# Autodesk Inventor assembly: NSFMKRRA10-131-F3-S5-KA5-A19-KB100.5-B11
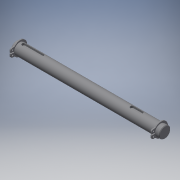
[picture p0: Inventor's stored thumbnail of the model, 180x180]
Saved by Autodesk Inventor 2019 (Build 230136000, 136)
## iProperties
Category: PARTsolutions
Company: MISUMI
Created: 2022-11
Part Number: NSFMKRRA10-131-F3-S5-KA5-A19-KB100.5-B11
Catalog Web Link: www.cadenas.de
Description: NSFMKRR, SFMKRR, PSFMKRR, SSFMKRR, NSFHKRR, SFHKRR, PSFHKRR, SSFHKRR, NSFGKRR, SFGKRR, PSFGKRR, SSFGKRR, NSFMKRRA, SFMKRRA, PSFMKRRA, SSFMKRRA, NSFHKRRA, SFHKRR
Vendor: MISUMI
Document SubType Name: Assembly
Designer: psAdmin
Manufacturer: MISUMI
Mass: 10.2368 g
Surface Area: 47.8895 cm^2
Volume: 10.2368 cm^3
Density: 1 g/cm^3
Title: NSFMKRRA10-131-F3-S5-KA5-A19-KB100.5-B11
Author: Cadenas PARTsolutions
Comments: Rotary Shafts - Retaining Ring Grooves on Both Ends with Keyway -
PSOL_IDENT_0: {$CADENAS_DATA/23d-libs/misumi/metric/11_rotary_shafts/psfgkrr_asmtab.prj},644 {VTYP=3D},{STYP=ASSTA
PSOL_IDENT_1: B},{NB=NSFMKRRA10-131-F3-S5-KA5-A19-KB100.5-B11},{LINA=NSFMKRRA10-131-F3-S5-KA5-A19-KB100.5-B11},{NN=
PSOL_IDENT_2: NSFMKRR, SFMKRR, PSFMKRR, SSFMKRR, NSFHKRR, SFHKRR, PSFHKRR, SSFHKRR, NSFGKRR, SFGKRR, PSFGKRR, SSFG
PSOL_IDENT_3: KRR, NSFMKRRA, SFMKRRA, PSFMKRRA, SSFMKRRA, NSFHKRRA, SFHKRRA, PSFHKRRA, SSFHKRRA, NSFGKRRA, SFGKRRA
PSOL_IDENT_4: , PSFGKRRA, SSFGKRRA},{DATE=25.01.2022 23:09:58},{GEOMDATE=05.02.2021 08:16:43},{VERSION=},{LINEID=3
PSOL_IDENT_5: 0},{WBVAR=TS,TYS,MAT,ST,ALT1,L,F,S,NOK,KA,A,KB,B,KC,C,ALT3,FC,GALT3,WFC,J,WALT3,V,ALT4,SFC,SG,AG,ALT
PSOL_IDENT_6: 10,KWC,ALT11,WC,ALT5,UC,ALT7,SC,ALT32,CD},{WBNUMERIC=L,F,S,KA,A,KB,B,KC,C,FC,GALT3,WFC,J,WALT3,V,SFC
PSOL_IDENT_7: ,SG,AG,KWC,WC,UC,SC}  {NB=NSFMKRRA10-131-F3-S5-KA5-A19-KB100.5-B11},{LINA=NSFMKRRA10-131-F3-S5-KA5-A
PSOL_IDENT_8: 19-KB100.5-B11},{KT=DUMMY},{PN=NSFMKRRA10-131-F3-S5-KA5-A19-KB100.5-B11},{TS=A},{TSALG='','Standard'
PSOL_IDENT_9: ,'A','Retaining Ring'},{TYS=M},{TYSALG= 'M','h9 (Cold-drawn)','H','h7 (Ground)','G','g6 (Ground)' },
PSOL_IDENT_10: {MAT=S45C},{MATALG= 'S45C','S45C Equivalent', 'SUS304','304 Stainless Steel' },{ST=},{STALG= '','-','
PSOL_IDENT_11: BO','Black Oxide', 'ENP','Electroless Nickel Plating' },{TYPE=NSFMKRR},{D=10},{ALT1=},{LKCMAX=799.9}
PSOL_IDENT_12: ,{L=131.0},{LALG=[15:800/0.1]},{LMIN=15},{LMAX=800},{F=3.0},{FALG=[3:126/0.1]},{FMIN=3},{FMAX1=122.8
PSOL_IDENT_13: },{FMIN2=6.2},{FMAX2=126},{S=5.0},{SALG=[3:126/0.1]},{SMIN1=3},{SMAX1=121},{SMIN2=6.2},{SMAX2=126},{
PSOL_IDENT_14: DD=9.6},{MM=1.15},{MMALG=1.2},{MMJ=2},{NOK=2},{NOKALG= '1', 'with 1 Key Groove', '2'  , 'with 2 Key
PSOL_IDENT_15: Grooves', '3'  , 'with 3 Key Grooves'},{CIFNOK1=0},{CIFNOK2=3},{CIFNOK3=0},{TOL1=0},{TOL2=3},{TOL3=0
PSOL_IDENT_16: },{BB=3},{TT=1.8},{KA=5.0},{KAALG=[5:116/0.1]},{KAMIN1=0},{KAMIN2=5},{KAMIN3=129.2},{KAMAX1=-1000},{
PSOL_IDENT_17: KAMAX2=116},{KAMAX3=-1000},{A=19.0},{AALG=[3:100/0.1]},{AMIN=3},{AMAX=100},{AMAX1=-1000},{AMAX2=100}
PSOL_IDENT_18: ,{AMAX3=-1000},{KAPN=-KA5-A19},{KB=100.5},{KBALG=[26:121/0.1]},{KBMIN1=26},{KBMIN2=26},{KBMIN3=129.2
PSOL_IDENT_19: },{KBMAX1=-1000},{KBMAX2=121},{KBMAX3=-1000},{B=11.0},{BALG=[3:23.5/0.1]},{BMIN=3},{BMAX=23.5},{BMAX
PSOL_IDENT_20: 1=-1000},{BMAX2=23.5},{BMAX3=-1000},{KBPN=-KB100.5-B11},{KC=0.0},{KCALG=[0]},{KCMIN1=113.5},{KCMIN2=
PSOL_IDENT_21: 113.5},{KCMIN3=129.2},{KCMAX1=-1000},{KCMAX2=-1000},{KCMAX3=-1000},{C=0.0},{CALG=0},{CMIN=3},{CMAX=-
PSOL_IDENT_22: 1000},{CMAX1=-1000},{CMAX2=-1000},{CMAX3=-1000},{CIFKA=5},{CIFKB=3},{CIFKC=3},{KCPN=},{ALT3=},{ALT3A
PSOL_IDENT_23: LG= '', 'w/o Set Screw Flat','FC','with FC (Adds a Set Screw Flat)','WFC','with WFC (Adds Two Set Sc
PSOL_IDENT_24: rew Flats)','FCWFC','with FC + WFC (Adds Three Set Screw Flats)' },{ALT3PN=},{FC=0},{FCALG=[0]},{FCM
PSOL_IDENT_25: IN=0},{FCMAX=130},{GALT3=0},{GALT3ALG=[0]},{GALT3MIN=1},{GALT3MAX=70},{GALT3MAX2=70},{GALT3MAX3=70},
PSOL_IDENT_26: {WFC=0},{WFCALG=[0]},{WFCMIN=0},{WFCMIN2=2},{WFCMAX=127},{WFCMAX2=-3},{WFCMAX3=-4},{J=0},{JALG=[0]},
PSOL_IDENT_27: {JMIN=1},{JMAX=70},{JMAX2=-2},{JMAX3=-5},{WALT3=0},{WALT3ALG=[0]},{WALT3MIN=0},{WALT3MIN2=133},{WALT
PSOL_IDENT_28: 3MAX=128},{WALT3MAX2=128},{V=0},{VALG=[0]},{VMIN=1},{VMAX=70},{VMAX2=70},{CIFFC=0},{ALT4=},{ALT4ALG=
PSOL_IDENT_29: '', 'w/o SFC (2 Set Screw Flats (Angle Specified))', 'SFC'  , 'with SFC (2 Set Screw Flats (Angle S
PSOL_IDENT_30: pecified))'},{ALT4PN=},{SFC=0},{SFCALG=[0]},{SFCMIN=0},{SFCMAX=130},{SG=0},{SGALG=[0]},{SGMIN=1},{SG
PSOL_IDENT_31: MAX=70},{AG=0},{AGALG=[0]},{H=0},{CIFSFC=0},{ALT10=},{ALT10ALG= '','Not applicable' },{KWC=0},{KWCAL
PSOL_IDENT_32: G=[0]},{KWCMIN=1},{KWCMAX=0},{WALT10=8},{ALT10PN=},{ALT11=},{ALT11ALG= '','Not applicable' },{WC=0.0
PSOL_IDENT_33: },{WCALG=[0]},{ALT11PN=},{ALT5=},{ALT5ALG= '', 'w/o UC (Slit Cam Groove)', 'UC', 'with UC (Slit Cam
PSOL_IDENT_34: Groove)'},{ALT5PN=},{UC=0},{UCALG=[0]},{UCMIN=1},{UCMAX=125},{DDALT5=0},{LL1=0},{ALT7=},{ALT7ALG= ''
PSOL_IDENT_35: , 'w/o SC (Wrench Flats)', 'SC', 'with SC (Wrench Flats)'},{ALT7PN=},{SC=0},{SCALG=[0]},{SCMIN=0},{S
PSOL_IDENT_36: CMAX=123},{LL2=0},{LL2ALG=8},{WALT7=0},{CIFSC=0},{ALT32=},{ALT32ALG= '','w/o CD (Changes Part D Cham
PSOL_IDENT_37: fering)','CD','with CD (Changes Part D Chamfering)' },{CD=},{CDALG= '','N/A' },{CD3D=0.5},{ALT32PN=}
PSOL_IDENT_38: ,{CIF323R=0},{CIF323L=0},{CIF324R=0},{CIF324L=0},{CIF3210=0},{CIF32F=0},{CIF32S=0},{ERRORPN=},{ERROR
PSOL_IDENT_39: KGALT3=OK},{ERRORKGALT4=OK},{ERRORKGALT5=OK},{ERRORKGALT7=OK},{ERRORKGALT10=OK},{ERRORRALT3=OK},{ERR
PSOL_IDENT_40: ORRALT4=NG},{ERRORRALT5=NG},{ERRORRALT7=NG},{ERRORRALT10=OK},{ERRORALT34=OK},{ERRORALT35=OK},{ERRORA
PSOL_IDENT_41: LT37=OK},{ERRORALT310=OK},{ERRORALT45=OK},{ERRORALT47=OK},{ERRORALT410=OK},{ERRORALT57=OK},{ERRORALT
PSOL_IDENT_42: 510=OK},{ERRORALT710=OK},{PCUT3D=0},{QCUT3D=0},{TTALT2=1.8},{BBALT2=3},{PPATH=11_components/psfgkrr/
PSOL_IDENT_43: psfgkrr_asmtpl.prj}
NB: NSFMKRRA10-131-F3-S5-KA5-A19-KB100.5-B11
NN: NSFMKRR, SFMKRR, PSFMKRR, SSFMKRR, NSFHKRR, SFHKRR, PSFHKRR, SSFHKRR, NSFGKRR, SFGKRR, PSFGKRR, SSFGKRR, NSFMKRRA, SFMKRRA, PSFMKRRA, SSFMKRRA, NSFHKRRA, SFHKRR
NT: Rotary Shafts - Retaining Ring Grooves on Both Ends with Keyway -
NBSYN: $PN.
LINA: NSFMKRRA10-131-F3-S5-KA5-A19-KB100.5-B11
CATALOG: Misumi
PN: NSFMKRRA10-131-F3-S5-KA5-A19-KB100.5-B11
TS: Retaining Ring
TYS: h9 (Cold-drawn)
MAT: S45C Equivalent
ST: -
D: 10
ALT1: w/o LKC (Changes L Tolerance)
L: 131
F: 3
S: 5
DD: 9.6
MM: 1.15
NOK: with 2 Key Grooves
KA: 5
A: 19
KB: 100.5
B: 11
KC: 0
C: 0
ALT3: w/o Set Screw Flat
FC: 0
GALT3: 0
WFC: 0
J: 0
WALT3: 0
V: 0
ALT4: w/o SFC (2 Set Screw Flats (Angle Specified))
SFC: 0
SG: 0
AG: 0
H: 0
ALT10: Not applicable
KWC: 0
ALT11: Not applicable
WC: 0
ALT5: w/o UC (Slit Cam Groove)
UC: 0
DDALT5: 0
LL1: 0
ALT7: w/o SC (Wrench Flats)
SC: 0
LL2: 0
WALT7: 0
ALT32: w/o CD (Changes Part D Chamfering)
CD: N/A
SUPPLIER: MISUMI
ARTICLENO: NSFMKRRA10-131-F3-S5-KA5-A19-KB100.5-B11
BOMINFO: NSFMKRRA10-131-F3-S5-KA5-A19-KB100.5-B11
CREATOR: CADENAS GmbH
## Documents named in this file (3)
- e:\temp\worker_COMMON_4\temp\tmp_3352_216_vlDo1\format_0\NSFMKRRA10-131-F3-S5-KA5-A19-KB100_5-B11.iam
- e:\temp\worker_COMMON_4\temp\tmp_3352_216_vlDo1\format_0\NSFMKRRA10-131-F3-S5-KA5-A19-KB100_5-B11_s.ipt
- e:\temp\worker_COMMON_4\temp\tmp_3352_216_vlDo1\format_0\STWS10.ipt
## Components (3 placed, 2 different names)
1. NSFMKRRA10-131-F3-S5-KA5-A19-KB100_5-B11_s:1 — to_rring_1_XY@1 <-> 1_XY@2, to_rring_1_Z@1 <-> 1_Z@2, to_rring_1_YZ@1 <-> 1_YZ@2, to_rring_2_XY@1 <-> 1_XY@3, to_rring_2_Z@1 <-> 1_Z@3, to_rring_2_YZ@1 <-> 1_YZ@3
2. STWS10:1 — to_rring_1_XY@1 <-> 1_XY@2, to_rring_1_Z@1 <-> 1_Z@2, to_rring_1_YZ@1 <-> 1_YZ@2
3. STWS10:2 — to_rring_2_XY@1 <-> 1_XY@3, to_rring_2_Z@1 <-> 1_Z@3, to_rring_2_YZ@1 <-> 1_YZ@3
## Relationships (6: Mate 4, Angle 2)
- to_rring_1_XY@1 <-> 1_XY@2 [Mate]: NSFMKRRA10-131-F3-S5-KA5-A19-KB100_5-B11_s:1 ↔ STWS10:1
- to_rring_1_Z@1 <-> 1_Z@2 [Mate]: NSFMKRRA10-131-F3-S5-KA5-A19-KB100_5-B11_s:1 ↔ STWS10:1
- to_rring_1_YZ@1 <-> 1_YZ@2 [Angle]: NSFMKRRA10-131-F3-S5-KA5-A19-KB100_5-B11_s:1 ↔ STWS10:1
- to_rring_2_XY@1 <-> 1_XY@3 [Mate]: NSFMKRRA10-131-F3-S5-KA5-A19-KB100_5-B11_s:1 ↔ STWS10:2
- to_rring_2_Z@1 <-> 1_Z@3 [Mate]: NSFMKRRA10-131-F3-S5-KA5-A19-KB100_5-B11_s:1 ↔ STWS10:2
- to_rring_2_YZ@1 <-> 1_YZ@3 [Angle]: NSFMKRRA10-131-F3-S5-KA5-A19-KB100_5-B11_s:1 ↔ STWS10:2
